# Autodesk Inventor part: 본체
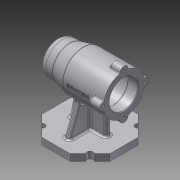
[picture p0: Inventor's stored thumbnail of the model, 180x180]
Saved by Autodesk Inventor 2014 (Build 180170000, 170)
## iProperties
Created: 2021-01
Part Number: 본체
Material: Aluminum 6061
Document SubType Name: Modeling
Designer: kh
Density: 2.71 g/cm^3
Appearance: Aluminum - Flat
Mass: 632.295 g
Surface Area: 613.786 cm^2
Volume: 233.319 cm^3
Author: kh
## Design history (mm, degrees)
sketch "Sketch1" dims "d1" = 100
  geometry: L1 (0, 0)-(0, 50); L2 (20.711, 50)-(50, 20.711); L3 (50, 20.711)-(50, -20.711); L4 (50, -20.711)-(20.711, -50); L5 (20.711, -50)-(-20.711, -50); L6 (-20.711, -50)-(-50, -20.711); L7 (-50, -20.711)-(-50, 20.711); L8 (-50, 20.711)-(-20.711, 50); L9 (-20.711, 50)-(20.711, 50); 2 further points
  constraints: 18 end point, 2 coincident, 1 midpoint, 1 vertical, 1 vertical alignment, 19 other
extrude "Extrusion1" new body sketch "Sketch1" distance "d2" = 10; taper "d3" = 0 deg
sketch "Sketch2"
  geometry: L1 (0, 0)-(50, 0); L2 (0, 0)-(35.355, 35.355); C1 r 4.5 at (35.355, 35.355); C2 r 4.5 at (-35.355, 35.355); C3 r 4.5 at (-35.355, -35.355); C4 r 4.5 at (35.355, -35.355); A1 r 50 centre (0, 0) between (50, 0) and (35.355, 35.355); 1 further point
  constraints: 5 centre point, 4 end point, 2 coincident, 2 point on circle, 1 horizontal, 9 other
  dimensions: "d4" = 100 diameter of A1; "d5" = 45 deg angle of L1 L2; "d6" = 9 diameter of C1; "d9" = 360 deg dimension on point (0, 0) C1.centre (derived)
extrude "Extrusion2" cut sketch "Sketch2" distance "d11" = 10; taper "d12" = 0 deg
sketch "Sketch3"
  geometry: L1 (20.711, 0)-(-20.711, 0) reference; L2 (0, 0)-(0, 75); L3 (50, 75)-(-50, 75); L4 (50, 75)-(50, 100); L5 (50, 100)-(30, 100); L6 (30, 100)-(10, 105); L7 (10, 105)-(-50, 105); L8 (-50, 105)-(-50, 75); L9 (-50, 96)-(-35, 96); L10 (-35, 96)-(-35, 99); L11 (-35, 99)-(7, 99); L12 (7, 99)-(7, 96); L13 (7, 96)-(19, 96); L14 (19, 96)-(19, 92.5); L15 (19, 92.5)-(37, 92.5); L16 (37, 92.5)-(37, 91); L17 (37, 91)-(41, 91); L18 (41, 91)-(41, 85.5); L19 (41, 85.5)-(44, 85.5); L20 (44, 85.5)-(44, 75)
  constraints: 38 end point, 12 perpendicular, 6 parallel, 2 point on line, 1 midpoint
  dimensions: "d13" = 75 distance of L2.end L2.start; "d14" = 100 distance of L3.start L3.end; "d15" = 20 distance from line of L5.end L4; "d16" = 40 distance from line of L6.end L4; "d17" = 50 diameter of L5 L3; "d18" = 60 diameter of L7 L3; "d19" = 42 diameter of L9 L3; "d20" = 48 diameter of L11 L3; "d21" = 42 diameter of L13 L3; "d22" = 35 diameter of L15 L3; "d23" = 32 diameter of L17 L3; "d24" = 21 diameter of L19 L3; "d25" = 15 distance of L9.start L9.end; "d26" = 42 distance of L10.end L11.end; "d27" = 12 distance of L12.end L13.end; "d28" = 18 distance of L14.end L15.end; "d29" = 4 distance of L16.end L17.end; "d30" = 3 distance of L18.end L19.end
revolve "Revolution1" sketch "Sketch3" stored, may be unused: angle "d31" = 90 deg
fillet "Fillet1" dims "d32" = 3
fillet "Fillet2" dims "d33" = 0.3
fillet "Fillet3" dims "d34" = 3
chamfer "Chamfer1" distance "d35" = 1; stored, may be unused: second distance "d36" = 2, angle "d37" = 45 deg
sketch "Sketch4"
  geometry: L1 (0, 0)-(-30, 0); C1 r 6 at (-30, 0); 1 further point
  constraints: 2 end point, 1 centre point, 1 coincident, 1 horizontal, 1 horizontal alignment, 1 other
  dimensions: "d39" = 12 diameter of C1
extrude "Extrusion3" join sketch "Sketch4" distance "d40" = 16; taper "d41" = 0 deg
pattern_circular "Circular Pattern1" dims angle "d43" = 360 deg
hole "Hole1" diameter "d47" = 3.242; stored, may be unused: countersink angle "d51" = 90 deg, drill point angle "d53" = 118 deg; dims "d45" = 10, "d46" = 10, "d48" = 8, "d49" = 4, "d50" = 2, "d52" = 10
pattern_circular "Circular Pattern2" dims angle "d55" = 360 deg
fillet "Fillet4" dims "d57" = 10
sketch "Sketch5"
  geometry: L1 (-4, -4)-(4, -4); L2 (4, -4)-(4, 4); L3 (4, 4)-(-4, 4); L4 (-4, 4)-(-4, -4); L5 (-4, -4)-(4, 4); L6 (4, -4)-(-4, 4); 1 further point
  constraints: 12 end point, 2 midpoint, 2 parallel, 1 horizontal, 1 perpendicular
  dimensions: "d60" = 8 distance of L2.end L3.end; "d61" = 8 distance of L1.end L2.end
extrude "Extrusion4" join sketch "Sketch5" stored distance "d62" = 16; taper "d63" = 0 deg
sketch "Sketch6"
  geometry: L1 (-50, 10)-(-38.537, 10) reference; L2 (-38.537, 10)-(-30.855, 10) reference; L3 (-27, 10)-(-27, 35.493); 2 further points
  constraints: 2 end point, 1 perpendicular, 1 point on line
  dimensions: "d64" = 23 distance of L1.start L3.start
feature "Rib1" sketch "Sketch6" dims "d65" = 1, "d66" = 8, "d67" = 0, "d68" = 0, "d69" = 1, "d70" = 1
sketch "Sketch7"
  geometry: L1 (38.537, 10)-(50, 10) reference; L2 (27, 10)-(22.664, 32.309); 1 further point
  constraints: 2 end point, 1 point on line
  dimensions: "d71" = 23 distance of L2.start L1.end; "d72" = 101 deg angle of L2 L1
feature "Rib2" sketch "Sketch7" dims "d73" = 1, "d74" = 8, "d75" = 0, "d76" = 0, "d77" = 1, "d78" = 1
sketch "Sketch8"
  geometry: L1 (50, 10)-(38.537, 10) reference; L2 (35, 10)-(27.043, 31.861); 1 further point
  constraints: 2 end point, 1 point on line
  dimensions: "d79" = 15 distance of L1.start L2.start; "d80" = 110 deg angle of L2 L1
feature "Rib3" sketch "Sketch8" dims "d81" = 1, "d82" = 8, "d83" = 0, "d84" = 0, "d85" = 1, "d86" = 1
mirror "Mirror1"
fillet "Fillet5" dims "d87" = 3
fillet "Fillet6" dims "d88" = 1
fillet "Fillet7" dims "d89" = 3
fillet "Fillet8" dims "d90" = 3
fillet "Fillet9" dims "d91" = 3
fillet "Fillet10" dims "d92" = 3
workplane "Work Plane1"
sketch "Sketch9"
  geometry: L1 (-24.592, 2.402)-(8.592, 2.402); L2 (8.592, 2.402)-(8.592, -2.402); L3 (8.592, -2.402)-(-24.592, -2.402); L4 (-24.592, -2.402)-(-24.592, 2.402); L5 (-8, 2.402)-(-8, -2.402); L6 (-24.592, 0)-(-8, 0); L7 (30, 36)-(30, 30.171) reference; L8 (-60, 25)-(-60, -25) reference; L9 (-60, 0)-(8.592, 0); 1 further point
  constraints: 6 end point, 5 midpoint, 1 perpendicular, 1 point on line, 2 other
  dimensions: "d93" = 38 distance from line of L5.start L7
emboss "Emboss1" sketch "Sketch9" dims "d1" = 100, "d4" = 100, "d5" = 45 deg, "d6" = 9, "d9" = 360 deg (derived), "d94" = 0.5, "d95" = 0
body "Solid1"
